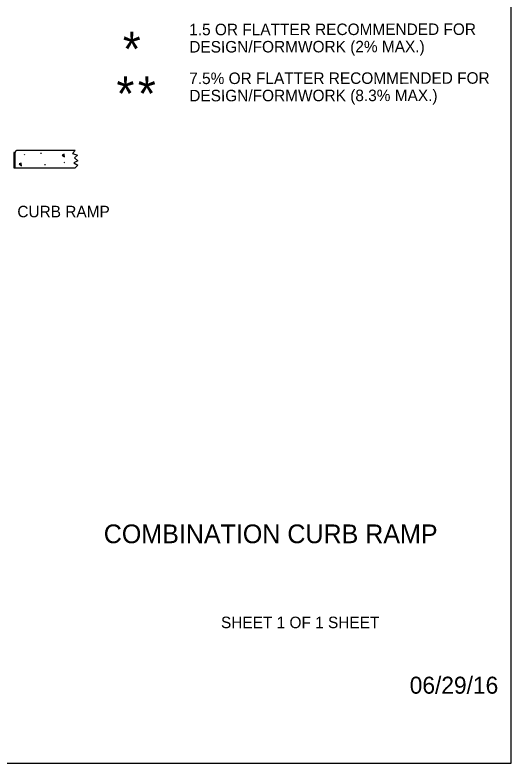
# Model space of a CAD drawing. Extents: x 103862 to 107151, y 100000 to 102076.
# Drawn here: x 106462 to 107151, y 100000 to 101038 of the extents above; entities that cross this region are included whole.
import ezdxf

# ---------------------------------------------------------------- set-up
doc = ezdxf.new("R2010")
doc.units = 0
for name, color, linetype in [('Level 1', 7, 'Continuous'), ('Level 15', 7, 'Continuous'), ('Level 20', 7, 'Continuous'), ('Level 6', 7, 'Continuous'), ('Level 62', 7, 'Continuous')]:
    doc.layers.add(name, color=color, linetype=linetype)

msp = doc.modelspace()

# ---------------------------------------------------------------- linework, layer by layer
at = {"layer": 'Level 1'}
msp.add_lwpolyline([(103862, 99999.5), (107151, 99999.5), (107151, 102075.5), (103862, 102075.5)], close=True, dxfattribs=at)
msp.add_lwpolyline([(103862, 99999.5), (107151, 99999.5), (107151, 102075.5), (103862, 102075.5)], close=True, dxfattribs=at)
msp.add_lwpolyline([(103862, 99999.5), (107151, 99999.5), (107151, 102075.5), (103862, 102075.5)], close=True, dxfattribs=at)
at = {"layer": 'Level 6'}
for p, q in [((106545.8, 100850.4), (106465.6, 100850.4)), ((106475.6, 100843.5), (106475.5, 100844.8)), ((106498.5, 100845.7), (106498.4, 100847)), ((106504.2, 100829.8), (106504.1, 100831.1)), ((106530.9, 100833.5), (106530.1, 100833)), ((106462.6, 100826.3), (106545.8, 100826.3))]:
    msp.add_line(p, q, dxfattribs=at)
for points in [[(106545.8, 100850.4), (106541.9, 100846), (106549.1, 100843.7), (106544.8, 100840.2), (106549.5, 100835.9), (106544, 100833.2), (106549.4, 100829.9), (106545.8, 100826.3)], [(106531, 100841.2), (106530.6, 100844.9), (106527.5, 100843.9), (106531, 100841.2)], [(106471.3, 100829), (106470.9, 100832.7), (106467.7, 100831.7), (106471.3, 100829)]]:
    msp.add_lwpolyline(points, dxfattribs=at)
msp.add_lwpolyline([(106462.6, 100847.4), (106460.4, 100847.4), (106460.4, 100826.3), (106462.6, 100826.3)], close=True, dxfattribs=at)
msp.add_arc((106465.6, 100847.4), 3, 90, 180, dxfattribs=at)

# ---------------------------------------------------------------- texts
at = {"layer": 'Level 15'}
msp.add_text('06/29/16', height=23.62, dxfattribs=at).set_placement((107010.3, 100095.8))
at = {"layer": 'Level 20'}
for s, rotation, p in [('1.5 OR FLATTER RECOMMENDED FOR', 0.0709, (106704.1, 101010.2)), ('DESIGN/FORMWORK (2% MAX.)', 0.0709, (106704.2, 100986.2)), ('7.5% OR FLATTER RECOMMENDED FOR', 0.0709, (106704.1, 100942.4)), ('DESIGN/FORMWORK (8.3% MAX.)', 0.0709, (106704.2, 100918.4)), ('CURB RAMP', 360, (106465.4, 100757.4))]:
    msp.add_text(s, height=16, rotation=rotation, dxfattribs=at).set_placement(p)
for p in [(106611.8, 100967.2), (106603, 100905.2), (106632.7, 100905.2)]:
    msp.add_text('*', height=48, dxfattribs=at).set_placement(p)
at = {"layer": 'Level 62'}
for s, height, p in [('COMBINATION CURB RAMP', 26, (106585.4, 100304.8)), ('SHEET 1 OF 1 SHEET', 16, (106748.2, 100186.8))]:
    msp.add_text(s, height=height, dxfattribs=at).set_placement(p)

doc.saveas('drawing.dxf')
